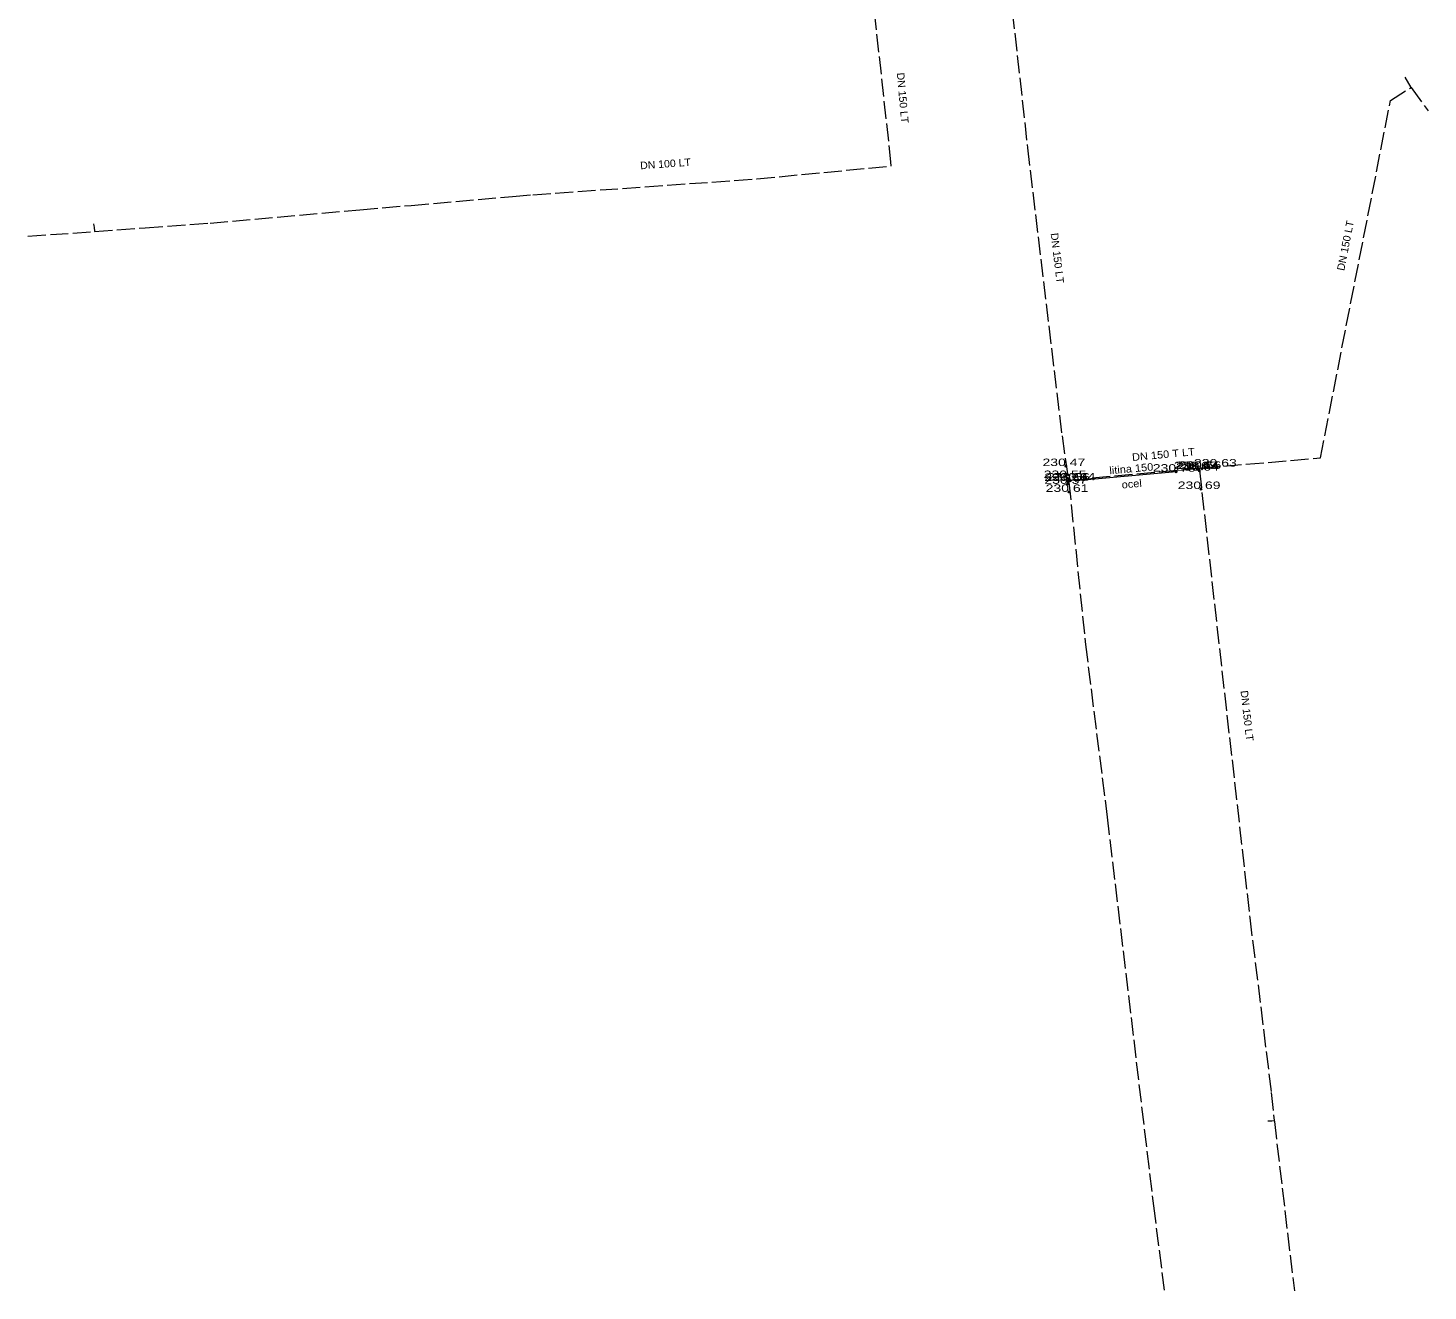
# Model space of a CAD drawing. Extents: x -642285 to -641979, y -1041680 to -1041425.
# Drawn here: x -642284.6 to -642144.1, y -1041679.6 to -1041552.9 of the extents above; entities that cross this region are included whole.
import ezdxf
from ezdxf.enums import TextEntityAlignment as Align

# ---------------------------------------------------------------- set-up
doc = ezdxf.new("R2010")
doc.units = 0
doc.header["$LTSCALE"] = 0.3
doc.header["$PDMODE"] = 32
doc.header["$PDSIZE"] = 0.15
doc.linetypes.add('LONG_DASHED', pattern=[7.5, 6, -1.5])
for name, color, linetype in [('1', 7, 'Continuous'), ('16', 7, 'Continuous'), ('20', 7, 'Continuous'), ('3', 7, 'Continuous')]:
    doc.layers.add(name, color=color, linetype=linetype)
doc.layers.add('25', color=7, linetype='Continuous', lineweight=13)
doc.layers.add('35', color=7, linetype='LONG_DASHED', lineweight=13)

msp = doc.modelspace()

# ---------------------------------------------------------------- linework, layer by layer
at = {"layer": '1'}
for p in [(-642180.43, -1041596.81), (-642169.36, -1041597.37), (-642167.24, -1041597.12), (-642167.06, -1041597.11), (-642167.03, -1041597.27), (-642166.78, -1041597.08), (-642165.23, -1041596.86), (-642180.31, -1041598.01), (-642180.25, -1041598.3), (-642180.24, -1041598.59), (-642179.97, -1041598.27), (-642179.4, -1041598.25), (-642166.86, -1041599.11), (-642180.11, -1041599.4)]:
    msp.add_point(p, dxfattribs=at)
at = {"layer": '25'}
msp.add_line((-642179.4, -1041598.25), (-642169.36, -1041597.37), dxfattribs=at)
at = {"layer": '35'}
for p, q in [((-642145.791, -1041558.826), (-642146.399, -1041557.82)), ((-642145.791, -1041558.826), (-642144.092, -1041561.193)), ((-642211.421, -1041567.999), (-642197.973, -1041566.72)), ((-642198.012, -1041566.281), (-642197.973, -1041566.72)), ((-642272.808, -1041572.918), (-642266.289, -1041572.439)), ((-642266.289, -1041572.439), (-642251.26, -1041571.112)), ((-642284.555, -1041573.762), (-642277.883, -1041573.283)), ((-642277.93, -1041572.85), (-642277.883, -1041573.283)), ((-642277.883, -1041573.283), (-642272.808, -1041572.918)), ((-642180.812, -1041593.793), (-642180.19, -1041598.03)), ((-642167.052, -1041597.018), (-642166.84, -1041597)), ((-642167.052, -1041597.018), (-642167.03, -1041597.21)), ((-642180.154, -1041598.23), (-642180.12, -1041598.42)), ((-642180.12, -1041598.42), (-642178.462, -1041614.701)), ((-642178.462, -1041614.701), (-642176.278, -1041632.024)), ((-642176.278, -1041632.024), (-642171.643, -1041671.003)), ((-642159.509, -1041662.549), (-642157.498, -1041679.551)), ((-642171.643, -1041671.003), (-642170.549, -1041679.551))]:
    msp.add_line(p, q, dxfattribs=at)
for points in [[(-642201.703, -1041526.103), (-642200.547, -1041536.893), (-642200.389, -1041544.544), (-642198.012, -1041566.281)], [(-642186.557, -1041544.447), (-642184.273, -1041564.886), (-642180.812, -1041593.793)], [(-642166.84, -1041597), (-642154.888, -1041595.998), (-642147.851, -1041560.142), (-642145.791, -1041558.826)], [(-642251.26, -1041571.112), (-642246.125, -1041570.659), (-642235.94, -1041569.777), (-642233.895, -1041569.6), (-642211.421, -1041567.999)], [(-642277.97, -1041572.5), (-642277.945, -1041572.716), (-642277.93, -1041572.85)], [(-642180.02, -1041598.21), (-642167.31, -1041597.04), (-642167.052, -1041597.018)], [(-642167.03, -1041597.21), (-642161.97, -1041642.13), (-642159.82, -1041659.649), (-642159.519, -1041662.462)], [(-642180.19, -1041598.03), (-642180.154, -1041598.23), (-642180.02, -1041598.21)], [(-642160.15, -1041662.5), (-642159.77, -1041662.49), (-642159.519, -1041662.462), (-642159.509, -1041662.549)]]:
    msp.add_lwpolyline(points, dxfattribs=at)

# ---------------------------------------------------------------- texts
at = {"layer": '16'}
for s, rotation, width, p in [('DN 150 LT', 275.077, 1.05, (-642197.388, -1041557.381)), ('DN 100 LT', 4.003, 1.05, (-642223.109, -1041567.046)), ('DN 150 LT', 78.896, 1.05, (-642152.5, -1041577.265)), ('DN 150 LT', 276.888, 1.05, (-642181.953, -1041573.475)), ('DN 150 T LT', 5.259, 1.1, (-642173.75, -1041596.305)), ('litina 150', 5.009, 1.1, (-642176.027, -1041597.631)), ('DN 150 LT', 276.492, 1.05, (-642162.904, -1041619.36))]:
    msp.add_text(s, height=0.75, rotation=rotation, dxfattribs=dict(at, width=width)).set_placement(p)
at = {"layer": '20', "width": 1.1}
msp.add_text('ocel', height=0.75, rotation=5.009, dxfattribs=at).set_placement((-642174.796, -1041599.061))
at = {"layer": '3', "width": 1.4}
for s, p in [('230 47 ', (-642180.43, -1041596.81)), ('230 67 ', (-642167.06, -1041597.11)), ('230 66 ', (-642166.78, -1041597.08)), ('230 63 ', (-642165.23, -1041596.86)), ('230 55 ', (-642180.31, -1041598.01)), ('230 56 ', (-642180.25, -1041598.3)), ('230 56 ', (-642179.97, -1041598.27)), ('230 64 ', (-642179.4, -1041598.25)), ('230 78 ', (-642169.36, -1041597.37)), ('230 67 ', (-642167.24, -1041597.12)), ('230 64 ', (-642167.03, -1041597.27)), ('230 57 ', (-642180.24, -1041598.59)), ('230 61 ', (-642180.11, -1041599.4)), ('230 69 ', (-642166.86, -1041599.11))]:
    msp.add_text(s, height=0.75, dxfattribs=at).set_placement(p, align=Align.CENTER)

doc.saveas('drawing.dxf')
